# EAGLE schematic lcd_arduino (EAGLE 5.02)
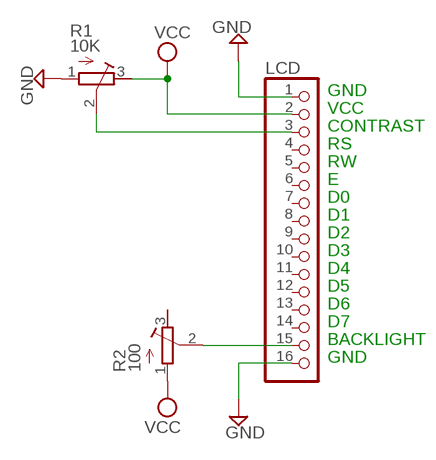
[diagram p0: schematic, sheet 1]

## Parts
LCD  PINHD-1X16  [1X16]
R1  10K  R-TRIMM4G/J  [RTRIM4G/J]
R2  100  R-TRIMM4G/J  [RTRIM4G/J]

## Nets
GND: LCD.1 LCD.16 R1.1(E)
N$1: LCD.3 R1.2(S)
N$2: LCD.15 R2.2(S)
VCC: LCD.2 R1.3(A) R2.1(E)
Unconnected: LCD.4 LCD.5 LCD.6 LCD.7 LCD.8 LCD.9 LCD.10 LCD.11 LCD.12 LCD.13 LCD.14 R2.3(A)

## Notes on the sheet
- GND
- VCC
- CONTRAST
- RS
- RW
- E
- D0
- D1
- D2
- D3
- D4
- D5
- D6
- D7
- BACKLIGHT
- GND

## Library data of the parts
LCD = pinhead:PINHD-1X16: PIN HEADER
R1 R2 = resistor:R-TRIMM: Trimm resistor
